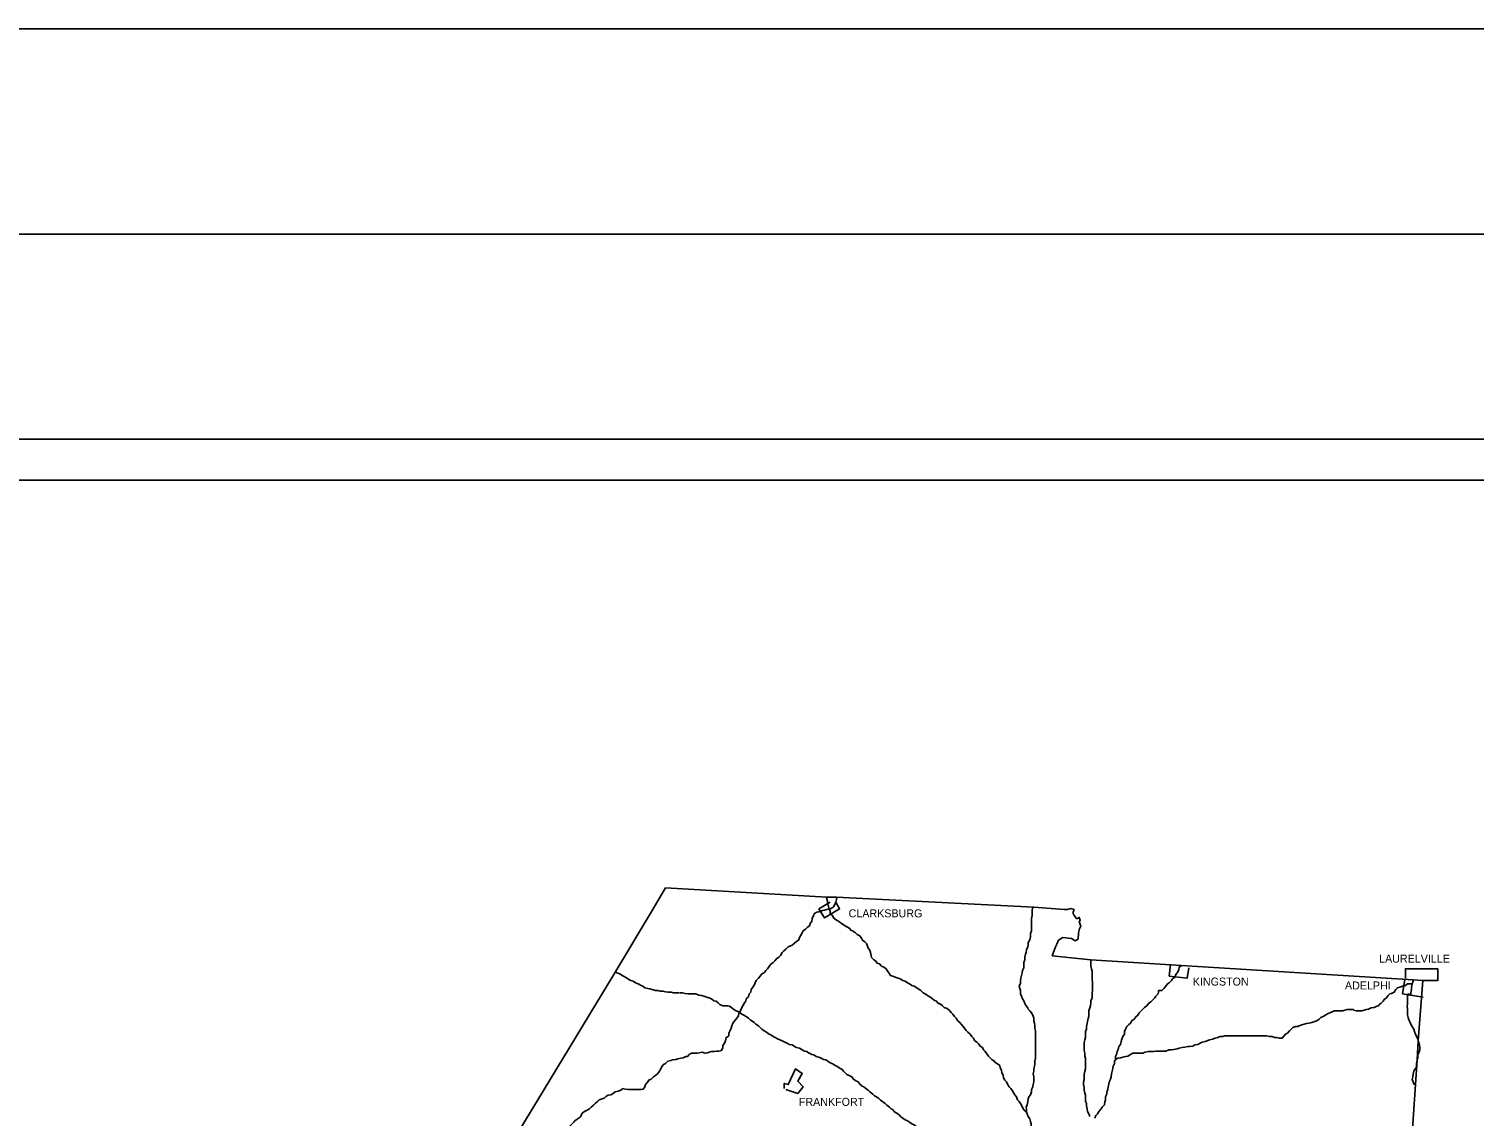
# Model space of a CAD drawing. Extents: x 0 to 34, y 0 to 22.
# Drawn here: x 3.569 to 7.09, y 19.351 to 22 of the extents above; entities that cross this region are included whole.
import ezdxf

# ---------------------------------------------------------------- set-up
doc = ezdxf.new("R2010")
doc.units = 0
for name, color, linetype in [('Default', 7, 'Continuous'), ('SH_Border', 7, 'Continuous'), ('SH_Cut_Line', 7, 'Continuous'), ('SH_Data', 7, 'Continuous')]:
    doc.layers.add(name, color=color, linetype=linetype)

msp = doc.modelspace()

# ---------------------------------------------------------------- linework, layer by layer
at = {"layer": 'Default'}
msp.add_line((6.9321, 19.6809), (6.9321, 19.6809), dxfattribs=at)
for points in [[(5.1201, 19.9072), (5.0874, 19.8513), (4.996, 19.7), (4.7438, 19.2827)], [(6.0622, 19.7409), (6.0704, 19.7627), (6.0731, 19.7695), (6.0772, 19.779), (6.0881, 19.7859), (6.1086, 19.7831), (6.1154, 19.779), (6.1181, 19.7777), (6.125, 19.7818), (6.1263, 19.7954), (6.1277, 19.8049), (6.1318, 19.8131), (6.1277, 19.824), (6.1304, 19.8281), (6.1277, 19.8349), (6.1236, 19.8322), (6.1209, 19.8322), (6.1154, 19.839), (6.1127, 19.8445), (6.1127, 19.8472), (6.1154, 19.854), (6.1072, 19.8567), (6.099, 19.854), (6.0909, 19.854), (6.0172, 19.8595), (5.536, 19.884), (5.5128, 19.884), (5.1201, 19.9072)], [(5.521, 19.8717), (5.4937, 19.8554), (5.5073, 19.8336), (5.5441, 19.8554), (5.5346, 19.8717)], [(5.5182, 19.8554), (5.5169, 19.8622), (5.5141, 19.869), (5.5141, 19.8745), (5.5128, 19.8799), (5.5114, 19.884)], [(5.5182, 19.8554), (5.5237, 19.8567), (5.5291, 19.8608), (5.5319, 19.8649), (5.5346, 19.8717), (5.536, 19.8786), (5.5373, 19.884)], [(5.4187, 19.7627), (5.4242, 19.7654), (5.4282, 19.7668), (5.4337, 19.7722), (5.4392, 19.7763), (5.4446, 19.7804), (5.446, 19.7859), (5.4487, 19.7899), (5.4528, 19.7968), (5.4555, 19.8022), (5.461, 19.8063), (5.4651, 19.8104), (5.4705, 19.8145), (5.4719, 19.8199), (5.476, 19.8254), (5.4773, 19.8322), (5.4801, 19.839), (5.4828, 19.8445), (5.4882, 19.8472), (5.4937, 19.8486), (5.5019, 19.8513), (5.5073, 19.8527), (5.5128, 19.854), (5.5182, 19.8554), (5.5182, 19.8554)], [(5.5687, 19.8077), (5.5619, 19.8118), (5.5578, 19.8145), (5.551, 19.8186), (5.5455, 19.8227), (5.5414, 19.8254), (5.536, 19.8281), (5.5291, 19.8336), (5.5264, 19.839), (5.521, 19.8431), (5.521, 19.8499), (5.5182, 19.8554)], [(6.0091, 19.7886), (6.0091, 19.7954), (6.0118, 19.8022), (6.0118, 19.8063), (6.0118, 19.8145), (6.0118, 19.8199), (6.0118, 19.8281), (6.0118, 19.8322), (6.0132, 19.839), (6.0132, 19.8458), (6.0132, 19.8527), (6.0145, 19.8595), (6.0145, 19.8595)], [(5.6096, 19.7709), (5.6055, 19.7749), (5.6, 19.779), (5.5973, 19.7845), (5.5932, 19.7899), (5.5864, 19.7927), (5.5823, 19.7968), (5.5755, 19.8022), (5.5714, 19.8036), (5.5687, 19.8077)], [(5.341, 19.6809), (5.3464, 19.6863), (5.3505, 19.6918), (5.3546, 19.6972), (5.3601, 19.7), (5.3642, 19.7054), (5.3683, 19.7095), (5.3723, 19.715), (5.3764, 19.7204), (5.3819, 19.7245), (5.386, 19.7286), (5.3901, 19.734), (5.3955, 19.7381), (5.3996, 19.7422), (5.4037, 19.749), (5.4078, 19.7531), (5.4132, 19.7572), (5.4187, 19.7627), (5.4187, 19.7627)], [(5.6355, 19.7231), (5.6314, 19.7286), (5.6273, 19.7313), (5.6218, 19.7368), (5.6205, 19.7422), (5.6191, 19.749), (5.6178, 19.7545), (5.6137, 19.7599), (5.6109, 19.7668), (5.6096, 19.7709)], [(6.0022, 19.6141), (5.9982, 19.6195), (5.9954, 19.625), (5.9927, 19.6318), (5.99, 19.6359), (5.9872, 19.6427), (5.9845, 19.6481), (5.9845, 19.6563), (5.9832, 19.6618), (5.9818, 19.6672), (5.9845, 19.6741), (5.9845, 19.6809), (5.9859, 19.6863), (5.9872, 19.6931), (5.9886, 19.7), (5.99, 19.7054), (5.9927, 19.7122), (5.9927, 19.7177), (5.9927, 19.7245), (5.9954, 19.7313), (5.9954, 19.7381), (5.9968, 19.7449), (5.9982, 19.749), (5.9995, 19.7559), (6.0022, 19.7627), (6.0036, 19.7668), (6.0036, 19.7736), (6.0077, 19.7804), (6.0091, 19.7872), (6.0091, 19.7886)], [(5.7037, 19.6795), (5.6982, 19.6809), (5.6914, 19.685), (5.6846, 19.6877), (5.6791, 19.689), (5.6737, 19.6918), (5.6682, 19.6931), (5.6641, 19.7), (5.66, 19.7054), (5.6573, 19.7095), (5.6518, 19.7136), (5.6464, 19.7163), (5.6409, 19.7218), (5.6355, 19.7231), (5.6355, 19.7231)], [(6.0622, 19.7409), (6.1563, 19.7313), (6.3772, 19.7177), (6.9416, 19.6822), (6.9648, 19.6809)], [(6.1536, 19.3496), (6.1509, 19.3564), (6.1481, 19.3618), (6.1468, 19.3686), (6.1454, 19.3755), (6.1454, 19.3809), (6.1427, 19.3864), (6.1427, 19.3945), (6.1427, 19.4014), (6.1413, 19.4068), (6.1399, 19.4136), (6.1399, 19.4205), (6.1386, 19.4273), (6.1386, 19.4341), (6.1399, 19.4395), (6.1399, 19.4464), (6.1399, 19.4518), (6.1413, 19.46), (6.1427, 19.4654), (6.1427, 19.4723), (6.1427, 19.4777), (6.1427, 19.4845), (6.1427, 19.4914), (6.1413, 19.4968), (6.1413, 19.5036), (6.1399, 19.5104), (6.1399, 19.5173), (6.1399, 19.5241), (6.1399, 19.5295), (6.1413, 19.5363), (6.1427, 19.5418), (6.1427, 19.55), (6.1427, 19.5568), (6.1454, 19.5622), (6.1454, 19.5691), (6.1468, 19.5759), (6.1481, 19.5813), (6.1495, 19.5882), (6.1509, 19.5936), (6.1509, 19.6018), (6.1509, 19.6072), (6.1536, 19.6141), (6.1549, 19.6195), (6.1563, 19.6263), (6.1563, 19.6318), (6.159, 19.6386), (6.159, 19.6441), (6.159, 19.6509), (6.1604, 19.6563), (6.1604, 19.6645), (6.1604, 19.67), (6.1604, 19.6768), (6.159, 19.6836), (6.159, 19.6904), (6.159, 19.6972), (6.159, 19.704), (6.1577, 19.7095), (6.1563, 19.7163), (6.1563, 19.7231), (6.1563, 19.7286), (6.1563, 19.73), (6.1563, 19.7313)], [(6.3499, 19.7204), (6.3472, 19.6918), (6.3908, 19.6863), (6.3949, 19.7122)], [(4.996, 19.704), (5.0015, 19.7), (5.0083, 19.6972), (5.0138, 19.6931), (5.0192, 19.6904), (5.0247, 19.6877), (5.0301, 19.6836), (5.0356, 19.6809), (5.041, 19.6795), (5.0465, 19.6754), (5.0533, 19.6727), (5.0601, 19.6686), (5.0642, 19.6672), (5.0697, 19.6631), (5.0765, 19.6618), (5.0819, 19.6604), (5.0874, 19.6591), (5.0956, 19.6563), (5.101, 19.6563), (5.1065, 19.655), (5.1133, 19.655), (5.1201, 19.6536), (5.1269, 19.6522), (5.1337, 19.6522), (5.1392, 19.6509), (5.146, 19.6509), (5.1528, 19.6509), (5.1542, 19.6509)], [(6.3226, 19.6563), (6.3295, 19.6563), (6.3336, 19.6618), (6.339, 19.6672), (6.3431, 19.6727), (6.3472, 19.6754), (6.3526, 19.6809), (6.3554, 19.685), (6.3608, 19.689), (6.3635, 19.6959), (6.3663, 19.7), (6.3704, 19.7068), (6.3717, 19.7136), (6.3772, 19.7177), (6.3772, 19.7177)], [(6.9226, 19.6863), (6.9226, 19.7095), (7.0016, 19.7095), (7.0016, 19.6809), (6.9648, 19.6809)], [(5.1556, 19.6509), (5.161, 19.6509), (5.1678, 19.6495), (5.1746, 19.6481), (5.1801, 19.6481), (5.1883, 19.6481), (5.1937, 19.6481), (5.2006, 19.6454), (5.2074, 19.6441), (5.2128, 19.6427), (5.2183, 19.6413), (5.2251, 19.6386), (5.2319, 19.6359), (5.2374, 19.6318), (5.2428, 19.6304), (5.2483, 19.6263)], [(5.3151, 19.6304), (5.3164, 19.6359), (5.3219, 19.6413), (5.3233, 19.6481), (5.3273, 19.6522), (5.3287, 19.6591), (5.3328, 19.6645), (5.3355, 19.67), (5.3383, 19.6754), (5.341, 19.6809), (5.341, 19.6809)], [(5.7841, 19.625), (5.78, 19.6304), (5.7746, 19.6331), (5.7691, 19.6372), (5.7636, 19.6413), (5.7582, 19.6441), (5.7527, 19.6481), (5.7473, 19.6509), (5.7418, 19.6563), (5.7377, 19.6591), (5.7323, 19.6631), (5.7255, 19.6672), (5.72, 19.6686), (5.7146, 19.6727), (5.7091, 19.6754), (5.7037, 19.6795), (5.7037, 19.6795)], [(6.2163, 19.4886), (6.2163, 19.4954), (6.219, 19.5009), (6.2204, 19.5077), (6.2231, 19.5132), (6.2245, 19.52), (6.2286, 19.5254), (6.2299, 19.5323), (6.2313, 19.5377), (6.234, 19.5445), (6.2381, 19.55), (6.2381, 19.5568), (6.2408, 19.5622), (6.2436, 19.5691), (6.2477, 19.5732), (6.2531, 19.5772), (6.2558, 19.5827), (6.2613, 19.5868), (6.2654, 19.5922), (6.2708, 19.5963), (6.2736, 19.6018), (6.279, 19.6072), (6.2831, 19.6113), (6.2872, 19.6154), (6.2927, 19.6195), (6.2967, 19.625), (6.3022, 19.6291), (6.3063, 19.6331), (6.3117, 19.6386), (6.3145, 19.6427), (6.3199, 19.6481), (6.3213, 19.6536), (6.3213, 19.6563), (6.3226, 19.6563)], [(6.8626, 19.625), (6.868, 19.6304), (6.8707, 19.6345), (6.8762, 19.6386), (6.8803, 19.6441), (6.8844, 19.6481), (6.8885, 19.6495), (6.8953, 19.6522), (6.8994, 19.6591), (6.9035, 19.6631), (6.9089, 19.6645), (6.9157, 19.6672), (6.9226, 19.6686), (6.928, 19.6727), (6.9335, 19.6727), (6.9389, 19.6727)], [(6.9212, 19.6836), (6.9157, 19.6481), (6.9662, 19.64)], [(6.9539, 19.5336), (6.9525, 19.5391), (6.9498, 19.5445), (6.9471, 19.55), (6.9444, 19.5568), (6.943, 19.5622), (6.9389, 19.5691), (6.9362, 19.5745), (6.9335, 19.58), (6.9307, 19.5854), (6.9294, 19.5909), (6.928, 19.5977), (6.928, 19.6045), (6.928, 19.6113), (6.9266, 19.6181), (6.928, 19.6236), (6.928, 19.6304), (6.928, 19.6359), (6.928, 19.6427), (6.9294, 19.6481), (6.9362, 19.6454), (6.9362, 19.6509), (6.9375, 19.6591), (6.9375, 19.6645), (6.9389, 19.6727), (6.9389, 19.6727)], [(6.9389, 19.6727), (6.9416, 19.6795), (6.9416, 19.6822)], [(6.9648, 19.6809), (6.9539, 19.5336), (6.9512, 19.4873), (6.9471, 19.4273)], [(5.2483, 19.6263), (5.2524, 19.6222), (5.2592, 19.6195), (5.2646, 19.6195), (5.2701, 19.6195), (5.2755, 19.6181), (5.281, 19.6141), (5.2864, 19.61), (5.2919, 19.6072), (5.2987, 19.6045), (5.3001, 19.6032)], [(5.3001, 19.6032), (5.3028, 19.6072), (5.3055, 19.6154), (5.3083, 19.6195), (5.3124, 19.6263), (5.3137, 19.6291), (5.3151, 19.6304)], [(5.9204, 19.4845), (5.915, 19.4886), (5.9109, 19.4927), (5.9068, 19.4968), (5.9027, 19.5023), (5.8986, 19.5077), (5.8945, 19.5118), (5.8918, 19.5173), (5.8864, 19.5213), (5.8823, 19.5268), (5.8782, 19.5309), (5.8727, 19.535), (5.87, 19.5404), (5.8659, 19.5445), (5.8618, 19.55), (5.8564, 19.5554), (5.8523, 19.5595), (5.8482, 19.565), (5.8454, 19.5691), (5.84, 19.5745), (5.8373, 19.5786), (5.8318, 19.5827), (5.8277, 19.5895), (5.8236, 19.5936), (5.8195, 19.5991), (5.8155, 19.6032), (5.8127, 19.6072), (5.8059, 19.6127), (5.7991, 19.6154), (5.795, 19.6195), (5.7895, 19.6236), (5.7868, 19.625), (5.7841, 19.625)], [(6.0213, 19.5009), (6.0213, 19.5077), (6.0213, 19.5145), (6.0213, 19.52), (6.0213, 19.5268), (6.0213, 19.5336), (6.0213, 19.5391), (6.0213, 19.5459), (6.0213, 19.5527), (6.0213, 19.5582), (6.02, 19.565), (6.02, 19.5704), (6.0186, 19.5772), (6.0172, 19.5827), (6.0172, 19.5895), (6.0145, 19.5963), (6.0118, 19.6018), (6.0077, 19.6072), (6.0036, 19.6113), (6.0022, 19.6141)], [(6.7958, 19.6086), (6.8026, 19.6072), (6.8094, 19.6072), (6.8162, 19.6072), (6.8217, 19.6086), (6.8271, 19.61), (6.8326, 19.6113), (6.8394, 19.6141), (6.8462, 19.6154), (6.853, 19.6181), (6.8571, 19.6195), (6.8612, 19.625), (6.8626, 19.625)], [(5.2742, 19.5459), (5.2742, 19.5527), (5.2769, 19.5595), (5.2796, 19.565), (5.281, 19.5704), (5.2837, 19.5772), (5.2864, 19.58)], [(5.2864, 19.58), (5.2905, 19.5854), (5.2933, 19.5895), (5.2974, 19.595), (5.2987, 19.6018), (5.3001, 19.6032)], [(5.3001, 19.6032), (5.3055, 19.5991), (5.311, 19.5963), (5.3164, 19.5936), (5.3219, 19.5895), (5.326, 19.5854), (5.3301, 19.5827), (5.3355, 19.5786), (5.3396, 19.5745), (5.3464, 19.5704), (5.3505, 19.5663), (5.3546, 19.5622), (5.3601, 19.5582), (5.3655, 19.5554), (5.371, 19.5513), (5.3764, 19.5486), (5.3819, 19.5445), (5.3873, 19.5418), (5.3928, 19.5391), (5.3982, 19.5363), (5.4037, 19.5336), (5.4105, 19.5309), (5.416, 19.5282), (5.4214, 19.5254), (5.4282, 19.5241), (5.4337, 19.52), (5.4392, 19.5173), (5.446, 19.5159), (5.4528, 19.5118), (5.4582, 19.5091), (5.4637, 19.5077), (5.4691, 19.5036), (5.4705, 19.5036)], [(6.6635, 19.5704), (6.6703, 19.5732), (6.6758, 19.5745), (6.6812, 19.5759), (6.688, 19.5772), (6.6949, 19.5786), (6.7017, 19.5813), (6.7071, 19.5827), (6.7126, 19.5868), (6.7167, 19.5909), (6.7221, 19.5936), (6.7289, 19.5977), (6.7344, 19.6004), (6.7385, 19.6018), (6.7439, 19.6045), (6.7494, 19.6072), (6.7562, 19.6072), (6.763, 19.6072), (6.7698, 19.6072), (6.7753, 19.6086), (6.7808, 19.61), (6.7889, 19.61), (6.7958, 19.61), (6.7958, 19.6086)], [(5.2387, 19.5077), (5.2442, 19.5091), (5.2496, 19.5091), (5.2565, 19.5104), (5.2592, 19.5173), (5.2592, 19.5227), (5.2633, 19.5282), (5.266, 19.5336), (5.2674, 19.5418), (5.2728, 19.5445), (5.2742, 19.5459)], [(6.2163, 19.4886), (6.2218, 19.4914), (6.2286, 19.4927), (6.234, 19.4941), (6.2408, 19.4954), (6.2463, 19.4968), (6.2531, 19.5009), (6.2586, 19.5036), (6.264, 19.5036), (6.2708, 19.5036), (6.2749, 19.5036), (6.2831, 19.5036), (6.2886, 19.5063), (6.2954, 19.5077), (6.3022, 19.5077), (6.309, 19.5077), (6.3145, 19.5091), (6.3213, 19.5091), (6.3281, 19.5091), (6.3336, 19.5091), (6.339, 19.5091), (6.3458, 19.5118), (6.3526, 19.5118), (6.3581, 19.5132), (6.3663, 19.5145), (6.3717, 19.5159), (6.3785, 19.5173), (6.3854, 19.5186), (6.3922, 19.52), (6.3963, 19.52), (6.4045, 19.5213), (6.4099, 19.5241), (6.4167, 19.5254), (6.4222, 19.5282), (6.4276, 19.5309), (6.4344, 19.5323), (6.4399, 19.5336), (6.4454, 19.5363), (6.4522, 19.5377), (6.459, 19.5404), (6.4658, 19.5418), (6.4713, 19.5445), (6.4781, 19.5445), (6.4822, 19.5459), (6.4835, 19.5459)], [(6.4835, 19.5459), (6.489, 19.5459), (6.4944, 19.5459), (6.5013, 19.5459), (6.5081, 19.5459), (6.5149, 19.5459), (6.5217, 19.5459), (6.5285, 19.5459), (6.534, 19.5459), (6.5422, 19.5459), (6.5476, 19.5459), (6.5544, 19.5459), (6.5599, 19.5459), (6.5667, 19.5459), (6.5735, 19.5459), (6.579, 19.5459), (6.5844, 19.5459), (6.5912, 19.5445), (6.5981, 19.5445), (6.6035, 19.5418), (6.609, 19.5418), (6.6158, 19.5404), (6.6226, 19.5404), (6.6253, 19.5445), (6.6308, 19.55), (6.6349, 19.5527), (6.6403, 19.5582), (6.6444, 19.5622), (6.6485, 19.5663), (6.6553, 19.5691), (6.6608, 19.5691), (6.6635, 19.5704)], [(6.9512, 19.4873), (6.9525, 19.4927), (6.9525, 19.5009), (6.9553, 19.505), (6.958, 19.5118), (6.958, 19.5173), (6.9566, 19.5241), (6.9553, 19.5309), (6.9539, 19.5336), (6.9539, 19.5336)], [(5.1092, 19.4682), (5.1119, 19.4723), (5.1147, 19.4764), (5.1201, 19.4791), (5.1256, 19.4845), (5.1324, 19.4859), (5.1365, 19.4873), (5.1447, 19.4886), (5.1501, 19.49), (5.1569, 19.4914), (5.1624, 19.4927), (5.1692, 19.4954), (5.1733, 19.4954), (5.1733, 19.4954)], [(5.1733, 19.4954), (5.1774, 19.5009), (5.1828, 19.5036), (5.191, 19.5036), (5.1965, 19.5036), (5.2019, 19.505), (5.2087, 19.5063), (5.2155, 19.5036), (5.2224, 19.505), (5.2265, 19.5063), (5.2319, 19.5077), (5.2374, 19.5077), (5.2387, 19.5077)], [(5.4705, 19.5036), (5.476, 19.5009), (5.4814, 19.4995), (5.4869, 19.4954), (5.4937, 19.4941), (5.4991, 19.4914), (5.5046, 19.4886), (5.51, 19.4873), (5.5155, 19.4845), (5.521, 19.4804), (5.5278, 19.4777), (5.5319, 19.475), (5.5373, 19.4723), (5.5428, 19.4682), (5.5469, 19.4654), (5.5482, 19.4654)], [(5.9995, 19.3605), (5.9954, 19.3632), (5.9913, 19.3686), (5.9886, 19.3741), (5.9845, 19.3809), (5.9818, 19.3864), (5.9777, 19.3905), (5.975, 19.3973), (5.9709, 19.4027), (5.9682, 19.4068), (5.9654, 19.4123), (5.9613, 19.4177), (5.9573, 19.4218), (5.9532, 19.4286), (5.9504, 19.4341), (5.9463, 19.4382), (5.9436, 19.4436), (5.9423, 19.4504), (5.9395, 19.4559), (5.9382, 19.4627), (5.9354, 19.4682), (5.9341, 19.4736), (5.9286, 19.4777), (5.9218, 19.4818), (5.9218, 19.4832), (5.9204, 19.4845)], [(5.9995, 19.3605), (5.9995, 19.3673), (5.9982, 19.3727), (6.0009, 19.3782), (6.0022, 19.3864), (6.0036, 19.3918), (6.005, 19.3973), (6.0091, 19.4027), (6.0118, 19.4095), (6.0118, 19.415), (6.0145, 19.4218), (6.0159, 19.4273), (6.0172, 19.4341), (6.0172, 19.4395), (6.0172, 19.4464), (6.0159, 19.4532), (6.0172, 19.46), (6.0172, 19.4654), (6.0186, 19.4723), (6.02, 19.4777), (6.02, 19.4845), (6.0213, 19.4914), (6.0213, 19.4954), (6.0213, 19.5009)], [(6.1659, 19.3455), (6.1686, 19.3523), (6.1727, 19.3564), (6.1754, 19.3618), (6.1809, 19.3686), (6.1836, 19.3727), (6.189, 19.3782), (6.1904, 19.385), (6.1918, 19.3905), (6.1918, 19.3973), (6.1945, 19.4027), (6.1958, 19.4109), (6.1972, 19.415), (6.1986, 19.4218), (6.1999, 19.4286), (6.2013, 19.4355), (6.204, 19.4409), (6.2054, 19.4464), (6.2068, 19.4532), (6.2081, 19.46), (6.2095, 19.4668), (6.2108, 19.4723), (6.2136, 19.4791), (6.2136, 19.4845), (6.2163, 19.4873), (6.2163, 19.4886)], [(6.9471, 19.4273), (6.943, 19.4286), (6.9416, 19.4341), (6.9389, 19.4395), (6.9403, 19.4464), (6.9416, 19.4532), (6.943, 19.46), (6.9457, 19.4641), (6.9498, 19.4695), (6.9498, 19.475), (6.9498, 19.4791), (6.9512, 19.4845), (6.9512, 19.4873)], [(5.0138, 19.4177), (5.0219, 19.4164), (5.0288, 19.415), (5.0356, 19.415), (5.041, 19.415), (5.0465, 19.415), (5.0547, 19.415), (5.0601, 19.415), (5.0656, 19.4164), (5.0697, 19.4218), (5.071, 19.4273), (5.0765, 19.4341), (5.0792, 19.4382), (5.0847, 19.4409), (5.0901, 19.4464), (5.0956, 19.4491), (5.101, 19.4545), (5.1051, 19.46), (5.1078, 19.4641), (5.1092, 19.4682)], [(5.4132, 19.415), (5.4419, 19.4055), (5.4555, 19.4218), (5.4419, 19.4355), (5.4528, 19.4545), (5.4364, 19.4654), (5.4187, 19.4273), (5.4092, 19.43), (5.4092, 19.4177)], [(5.5482, 19.4654), (5.5537, 19.46), (5.5578, 19.4559), (5.5619, 19.4518), (5.5673, 19.4491), (5.5741, 19.4464), (5.5782, 19.4409), (5.5837, 19.4368), (5.5891, 19.4341), (5.5932, 19.4286), (5.5987, 19.4232), (5.6028, 19.4218), (5.6082, 19.4177), (5.6137, 19.4136), (5.6178, 19.4095), (5.6246, 19.4041), (5.6287, 19.4), (5.6341, 19.3973), (5.6396, 19.3932), (5.6437, 19.3891), (5.6491, 19.385), (5.6546, 19.3809), (5.6587, 19.3768), (5.6655, 19.3727), (5.6696, 19.3686), (5.675, 19.3646), (5.6764, 19.3618), (5.6764, 19.3618)], [(4.917, 19.3577), (4.9224, 19.3618), (4.9292, 19.3646), (4.9347, 19.3686), (4.9388, 19.3727), (4.9442, 19.3768), (4.9483, 19.3809), (4.9538, 19.3864), (4.9579, 19.3905), (4.9633, 19.3918), (4.9701, 19.3945), (4.9742, 19.3986), (4.9797, 19.4014), (4.9865, 19.4027), (4.9919, 19.4055), (4.9974, 19.4095), (5.0042, 19.4109), (5.011, 19.4136), (5.0138, 19.4164), (5.0138, 19.4177), (5.0138, 19.4177)], [(6.9471, 19.4273), (6.9362, 19.2582), (6.9103, 18.871), (6.8994, 18.6992), (6.883, 18.5029)], [(4.827, 19.2746), (4.8311, 19.28), (4.8379, 19.2827), (4.842, 19.2882), (4.8474, 19.2923), (4.8502, 19.2964), (4.857, 19.3005), (4.8611, 19.3046), (4.8665, 19.3087), (4.872, 19.3127), (4.8747, 19.3168), (4.8815, 19.3223), (4.8856, 19.325), (4.8911, 19.3305), (4.8965, 19.3359), (4.8992, 19.3386), (4.9047, 19.3427), (4.9115, 19.3482), (4.9142, 19.3523), (4.9156, 19.3564), (4.917, 19.3577)], [(5.6764, 19.3618), (5.6832, 19.3577), (5.6887, 19.3536), (5.6927, 19.3496), (5.6982, 19.3455), (5.7037, 19.3414), (5.7091, 19.3386), (5.7146, 19.3359), (5.72, 19.3318), (5.7255, 19.3291), (5.7309, 19.325), (5.7364, 19.3237), (5.7418, 19.3209), (5.7473, 19.3196), (5.7527, 19.3168), (5.7596, 19.3141), (5.765, 19.3127), (5.7718, 19.3114), (5.7786, 19.3114), (5.7827, 19.31), (5.7827, 19.31)], [(6.0145, 19.2991), (6.0132, 19.3073), (6.0118, 19.3127), (6.0118, 19.3196), (6.0104, 19.325), (6.0104, 19.3318), (6.0091, 19.3373), (6.0077, 19.3441), (6.0036, 19.3496), (6.0009, 19.3564), (5.9995, 19.3605), (5.9995, 19.3605)]]:
    msp.add_lwpolyline(points, dxfattribs=at)
at = {"layer": 'SH_Border'}
msp.add_lwpolyline([(1.5, 21.5), (33.5, 21.5), (33.5, 0.5), (1.5, 0.5)], close=True, dxfattribs=at)
at = {"layer": 'SH_Cut_Line'}
msp.add_lwpolyline([(0, 0), (34, 0), (34, 22), (0, 22)], close=True, dxfattribs=at)
at = {"layer": 'SH_Data'}
for p, q in [((2, 21), (9, 21)), ((2.1, 20.9), (8.9, 20.9))]:
    msp.add_line(p, q, dxfattribs=at)

# ---------------------------------------------------------------- texts
at = {"layer": 'Default'}
for s, height, p in [('CLARKSBURG', 0.0195, (5.5659, 19.8349)), ('LAURELVILLE', 0.019502, (6.8585, 19.7245)), ('KINGSTON', 0.0195, (6.4045, 19.6686)), ('ADELPHI', 0.0195, (6.7753, 19.6591)), ('FRANKFORT', 0.0195, (5.4446, 19.3755))]:
    msp.add_text(s, height=height, dxfattribs=at).set_placement(p)

doc.saveas('drawing.dxf')
